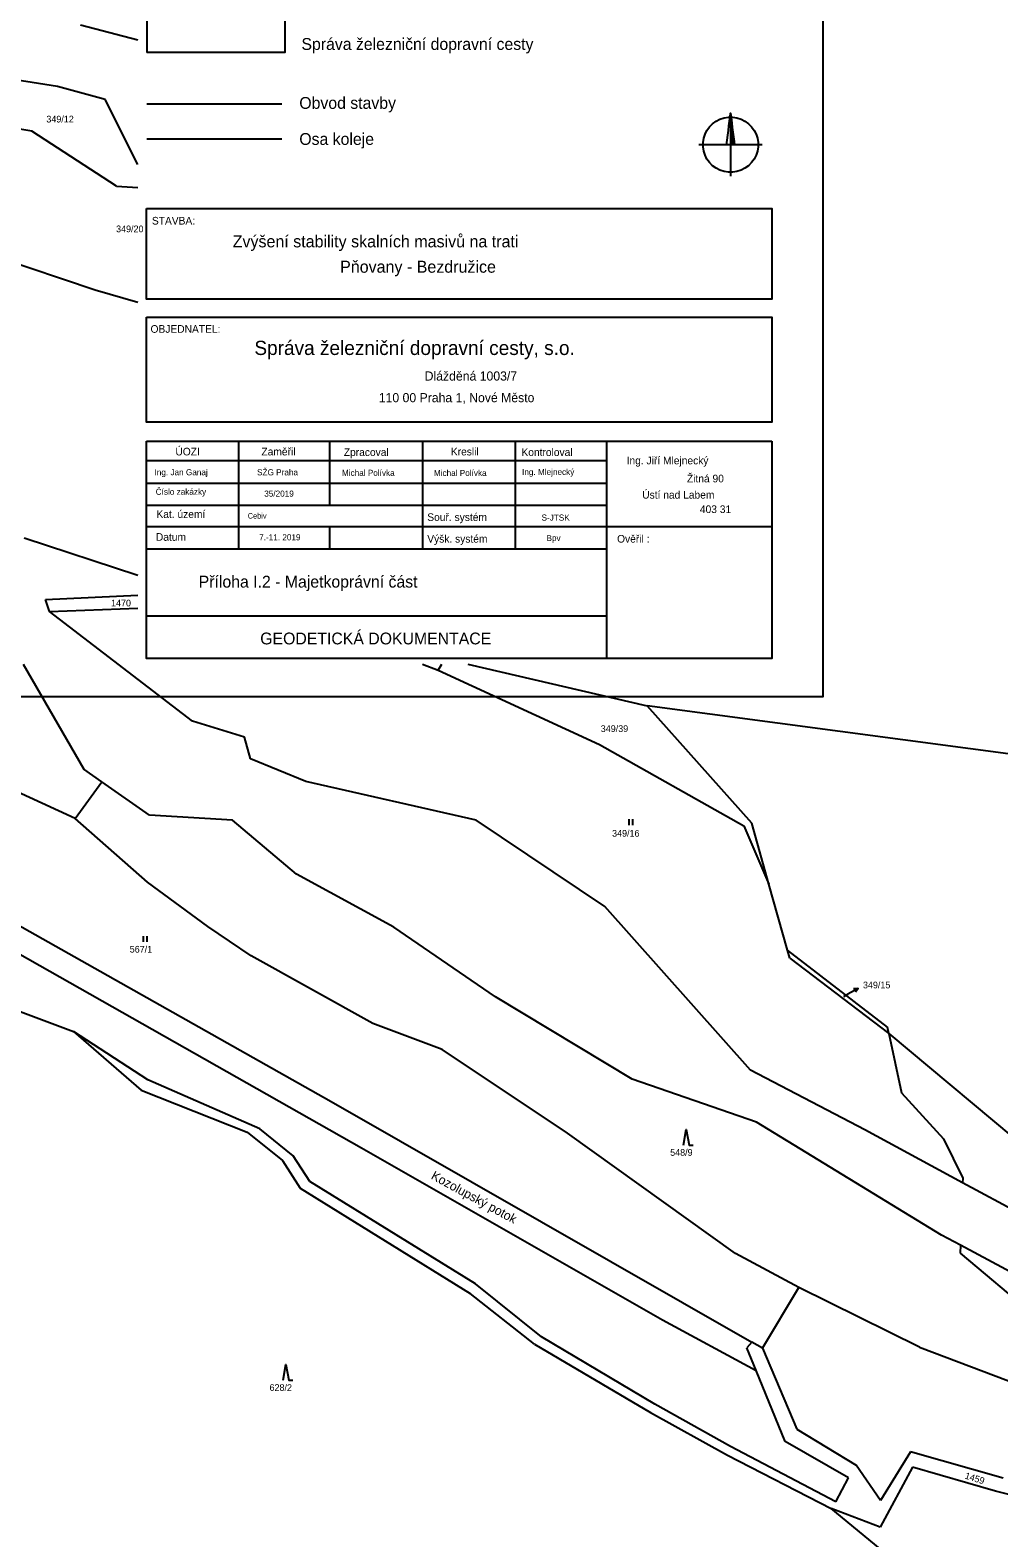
# Model space of a CAD drawing. Extents: x -852001 to -842497, y -1063614 to -1052182.
# Drawn here: x -848517.5 to -848271.7, y -1057263.9 to -1056881.4 of the extents above; entities that cross this region are included whole.
import ezdxf

# ---------------------------------------------------------------- set-up
doc = ezdxf.new("R2010")
doc.units = 0
for name, color, linetype in [('Default', 7, 'Continuous'), ('KN_HRANICE', 7, 'Continuous'), ('KN_KULTURY', 7, 'Continuous'), ('KN_PARCELY', 7, 'Continuous'), ('LEGENDA', 7, 'Continuous'), ('tabulka', 7, 'Continuous')]:
    doc.layers.add(name, color=color, linetype=linetype)

# ---------------------------------------------------------------- blocks, each defined once
blk = doc.blocks.new('306')
at = {"layer": 'Default'}
for p, q in [((-0.5, 1.5), (-0.5, 0)), ((0.5, 0), (0.5, 1.5))]:
    blk.add_line(p, q, dxfattribs=at)
blk = doc.blocks.new('308')
at = {"layer": 'Default'}
blk.add_lwpolyline([(-0.75, 0), (0, 4), (0.75, 0), (1.75, 0)], dxfattribs=at)
blk = doc.blocks.new('10292')
at = {"layer": 'Default'}
blk.add_line((0, 3), (0, 0), dxfattribs=at)
blk.add_lwpolyline([(-0.5, 2), (0, 3), (0.5, 2)], dxfattribs=at)
blk = doc.blocks.new('SEVER')
at = {"layer": 'Default'}
for points in [[(-10, 0), (-8.5, 12), (-7, 24), (-5.5, 36), (-4, 48), (-2.5, 60), (-1, 72), (0, 80), (1.5, 68), (3, 56), (4.5, 44), (6, 32), (7.5, 20), (9, 8), (10, 0), (9.2, 0.8), (9.2, 5.6), (8.4, 12), (8.4, 0.8), (7.6, 0.8), (7.6, 13.5), (7.6, 18.4), (6.8, 24.8), (6.8, 12.1), (6.8, 0.8), (6, 0.8), (6, 13.5), (6, 26.2), (6, 31.2), (5.2, 36.8), (5.2, 24.1), (5.2, 11.4), (5.2, 0.8), (4.4, 0.8), (4.4, 13.5), (4.4, 26.2), (4.4, 38.9), (4.4, 43.2), (3.6, 50.4), (3.6, 37.7), (3.6, 25), (3.6, 12.3), (3.6, 0.8), (2.8, 0.8), (2.8, 13.5), (2.8, 26.2), (2.8, 38.9), (2.8, 51.6), (2.8, 56), (2, 63.2), (2, 50.5), (2, 37.8), (2, 25.1), (2, 12.4), (2, 0.8), (1.2, 0.8), (1.2, 13.5), (1.2, 26.2), (1.2, 38.9), (1.2, 51.6), (1.2, 64.3), (1.2, 69.6), (0.4, 76), (0.4, 63.3), (0.4, 50.6), (0.4, 37.9), (0.4, 25.2), (0.4, 12.5), (0.4, 0.8)], [(0, 80), (0, 67.3), (0, 54.6), (0, 41.9), (0, 29.2), (0, 16.5), (0, 3.8), (0, -8.9), (0, -21.6), (0, -34.3), (0, -47), (0, -59.7), (0, -72.4), (0, -80)], [(5.5, 69.8), (16.3, 68.1), (26.7, 64.7), (36.5, 59.7), (45.4, 53.2), (53.2, 45.4), (59.7, 36.5), (64.7, 26.7), (68.1, 16.3), (69.8, 5.5), (69.8, -5.5), (68.1, -16.3), (64.7, -26.7), (59.7, -36.5), (53.2, -45.4), (45.4, -53.2), (36.5, -59.7), (26.7, -64.7), (16.3, -68.1), (5.5, -69.8), (-5.5, -69.8), (-16.3, -68.1), (-26.7, -64.7), (-36.5, -59.7), (-45.4, -53.2), (-53.2, -45.4), (-59.7, -36.5), (-64.7, -26.7), (-68.1, -16.3), (-69.8, -5.5), (-69.8, 5.5), (-68.1, 16.3), (-64.7, 26.7), (-59.7, 36.5), (-53.2, 45.4), (-45.4, 53.2), (-36.5, 59.7), (-26.7, 64.7), (-16.3, 68.1), (-5.5, 69.8), (5.5, 69.8)], [(80, 0), (67.3, 0), (54.6, 0), (41.9, 0), (29.2, 0), (16.5, 0), (3.8, 0), (-8.9, 0), (-21.6, 0), (-34.3, 0), (-47, 0), (-59.7, 0), (-72.4, 0), (-80, 0)]]:
    blk.add_lwpolyline(points, dxfattribs=at)

msp = doc.modelspace()

# ---------------------------------------------------------------- linework, layer by layer
at = {"layer": 'KN_HRANICE'}
for p, q in [((-848504.72, -1056880.07), (-848490.15, -1056883.83)), ((-848510.51, -1056895.7), (-848533.12, -1056892.09)), ((-848498.47, -1056899.01), (-848510.51, -1056895.7)), ((-848490.15, -1056915.49), (-848498.47, -1056899.01)), ((-848517.02, -1056907.05), (-848536, -1056903.82)), ((-848495.58, -1056920.99), (-848517.02, -1056907.05)), ((-848495.58, -1056920.99), (-848490.15, -1056921.28)), ((-848537.27, -1056935.01), (-848500.98, -1056947.31)), ((-848500.98, -1056947.31), (-848490.15, -1056950.37)), ((-848518.98, -1057010.18), (-848490.15, -1057019.65)), ((-848513.63, -1057025.87), (-848490.15, -1057024.73)), ((-848512.6, -1057028.9), (-848513.63, -1057025.87)), ((-848512.6, -1057028.9), (-848490.15, -1057028.02)), ((-848476.32, -1057056.74), (-848512.6, -1057028.9)), ((-848417.96, -1057042.22), (-848414, -1057043.75)), ((-848414, -1057043.75), (-848413.02, -1057042.22)), ((-848406.4, -1057042.22), (-848360.93, -1057052.81)), ((-848519.3, -1057042.27), (-848503.9, -1057068.91)), ((-848414, -1057043.75), (-848373.02, -1057062.67)), ((-848215.69, -1057072.14), (-848360.93, -1057052.81)), ((-848334.41, -1057082.61), (-848360.93, -1057052.81)), ((-848463.07, -1057060.76), (-848476.32, -1057056.74)), ((-848461.56, -1057066.3), (-848463.07, -1057060.76)), ((-848506.04, -1057081.45), (-848549.47, -1057061.41)), ((-848373.02, -1057062.67), (-848336.42, -1057083.27)), ((-848499.28, -1057072.14), (-848503.9, -1057068.91)), ((-848447.56, -1057072), (-848461.56, -1057066.3)), ((-848506.04, -1057081.45), (-848499.28, -1057072.14)), ((-848487.18, -1057080.6), (-848499.28, -1057072.14)), ((-848404.36, -1057081.83), (-848447.56, -1057072)), ((-848487.71, -1057097.61), (-848506.04, -1057081.45)), ((-848466.12, -1057081.86), (-848487.18, -1057080.6)), ((-848449.89, -1057095.52), (-848466.12, -1057081.86)), ((-848371.65, -1057103.72), (-848404.36, -1057081.83)), ((-848336.42, -1057083.27), (-848330.02, -1057098.12)), ((-848330.02, -1057098.12), (-848334.41, -1057082.61)), ((-848425.24, -1057108.98), (-848449.89, -1057095.52)), ((-848472.4, -1057108.82), (-848487.71, -1057097.61)), ((-848325.31, -1057114.79), (-848330.02, -1057098.12)), ((-848530.27, -1057102.96), (-848441.09, -1057153.24)), ((-848334.72, -1057145.28), (-848371.65, -1057103.72)), ((-848461.38, -1057116.29), (-848472.4, -1057108.82)), ((-848399.37, -1057126.68), (-848425.24, -1057108.98)), ((-848523.24, -1057114.03), (-848433.37, -1057164.99)), ((-848324.73, -1057116.84), (-848325.31, -1057114.79)), ((-848299.92, -1057134.4), (-848325.31, -1057114.79)), ((-848553.53, -1057117.8), (-848506.45, -1057135.5)), ((-848430.53, -1057133.44), (-848461.38, -1057116.29)), ((-848324.73, -1057116.84), (-848299.58, -1057135.99)), ((-848364.72, -1057147.55), (-848399.37, -1057126.68)), ((-848412.95, -1057140.06), (-848430.53, -1057133.44)), ((-848487.59, -1057147.75), (-848506.45, -1057135.5)), ((-848506.45, -1057135.5), (-848489.36, -1057150.38)), ((-848299.58, -1057135.99), (-848299.92, -1057134.4)), ((-848299.58, -1057135.99), (-848233.15, -1057191.58)), ((-848299.58, -1057135.99), (-848296.41, -1057151.03)), ((-848381.12, -1057161.25), (-848412.95, -1057140.06)), ((-848305.73, -1057160.43), (-848334.72, -1057145.28)), ((-848459.18, -1057160.12), (-848487.59, -1057147.75)), ((-848333.2, -1057158.46), (-848364.72, -1057147.55)), ((-848489.36, -1057150.38), (-848462.42, -1057161.04)), ((-848296.41, -1057151.03), (-848285.71, -1057162.73)), ((-848441.09, -1057153.24), (-848334.38, -1057214.31)), ((-848450.79, -1057166.98), (-848459.18, -1057160.12)), ((-848286.21, -1057187.14), (-848333.2, -1057158.46)), ((-848280.88, -1057173.84), (-848305.73, -1057160.43)), ((-848462.42, -1057161.04), (-848453.48, -1057168.21)), ((-848338.5, -1057191.75), (-848381.12, -1057161.25)), ((-848285.71, -1057162.73), (-848280.84, -1057172.68)), ((-848453.48, -1057168.21), (-848449.01, -1057175.25)), ((-848446.5, -1057173.48), (-848450.79, -1057166.98)), ((-848433.37, -1057164.99), (-848357, -1057208.66)), ((-848449.01, -1057175.25), (-848405.84, -1057201.9)), ((-848404.5, -1057199.51), (-848446.5, -1057173.48)), ((-848280.84, -1057172.68), (-848280.88, -1057173.84)), ((-848266.13, -1057181.8), (-848280.88, -1057173.84)), ((-848281.42, -1057189.71), (-848286.21, -1057187.14)), ((-848281.42, -1057189.71), (-848281.49, -1057191.69)), ((-848262.98, -1057199.6), (-848281.42, -1057189.71)), ((-848322.41, -1057200.38), (-848338.5, -1057191.75)), ((-848281.49, -1057191.69), (-848258.56, -1057211.07)), ((-848389.49, -1057214.83), (-848405.84, -1057201.9)), ((-848387.72, -1057212.93), (-848404.5, -1057199.51)), ((-848331.65, -1057215.79), (-848322.41, -1057200.38)), ((-848291.86, -1057215.56), (-848322.41, -1057200.38)), ((-848357, -1057208.66), (-848333.29, -1057221.51)), ((-848359, -1057230.02), (-848387.72, -1057212.93)), ((-848334.38, -1057214.31), (-848335.67, -1057215.72)), ((-848331.65, -1057215.79), (-848334.38, -1057214.31)), ((-848389.49, -1057214.83), (-848360.1, -1057232.1)), ((-848333.29, -1057221.51), (-848335.67, -1057215.72)), ((-848331.65, -1057215.79), (-848322.99, -1057236.35)), ((-848291.86, -1057215.56), (-848236.63, -1057236.51)), ((-848325.9, -1057239.53), (-848333.29, -1057221.51)), ((-848360.1, -1057232.1), (-848340.57, -1057242.94)), ((-848339.78, -1057240.74), (-848359, -1057230.02)), ((-848322.99, -1057236.35), (-848307.86, -1057245.53)), ((-848313.04, -1057254.78), (-848339.78, -1057240.74)), ((-848309.85, -1057248.75), (-848325.9, -1057239.53)), ((-848340.57, -1057242.94), (-848314.23, -1057256.53)), ((-848294.1, -1057242.15), (-848301.7, -1057254.43)), ((-848270.59, -1057248.8), (-848294.1, -1057242.15)), ((-848313.04, -1057254.78), (-848309.85, -1057248.75)), ((-848301.7, -1057254.43), (-848307.86, -1057245.53)), ((-848293.61, -1057246), (-848301.77, -1057261.22)), ((-848272.56, -1057252.1), (-848293.61, -1057246)), ((-848254.71, -1057256.58), (-848272.56, -1057252.1)), ((-848301.77, -1057261.22), (-848314.23, -1057256.53)), ((-848263.91, -1057297.71), (-848314.23, -1057256.53))]:
    msp.add_line(p, q, dxfattribs=at)
at = {"layer": 'KN_PARCELY'}
msp.add_line((-848311.02, -1057126.58), (-848310.02, -1057126.01), dxfattribs=at)
at = {"layer": 'LEGENDA'}
for p, q in [((-848487.86, -1056877.05), (-848487.86, -1056887.05)), ((-848487.84, -1056900.09), (-848453.65, -1056900.09)), ((-848487.84, -1056908.92), (-848453.65, -1056908.92))]:
    msp.add_line(p, q, dxfattribs=at)
msp.add_lwpolyline([(-848910.31, -1057050.45), (-848316.31, -1057050.45), (-848316.31, -1056630.45), (-848910.31, -1056630.45)], close=True, dxfattribs=at)
msp.add_lwpolyline([(-848452.86, -1056877.05), (-848452.86, -1056887.05), (-848487.86, -1056887.05)], dxfattribs=at)
at = {"layer": 'tabulka'}
for p, q in [((-848487.93, -1056985.69), (-848329.28, -1056985.69)), ((-848464.65, -1056985.69), (-848464.65, -1057013.01)), ((-848441.5, -1056985.69), (-848441.5, -1057001.89)), ((-848417.9, -1056985.69), (-848417.9, -1057013.01)), ((-848394.45, -1056985.69), (-848394.45, -1057013.01)), ((-848371.15, -1057040.83), (-848371.15, -1056985.69)), ((-848487.93, -1056990.6), (-848371.15, -1056990.6)), ((-848487.93, -1056996.32), (-848371.15, -1056996.32)), ((-848487.93, -1057001.89), (-848371.15, -1057001.89)), ((-848487.93, -1057007.31), (-848329.28, -1057007.31)), ((-848441.5, -1057007.31), (-848441.5, -1057013.01)), ((-848487.93, -1057013.01), (-848371.15, -1057013.01)), ((-848487.93, -1057030.01), (-848371.15, -1057030.01))]:
    msp.add_line(p, q, dxfattribs=at)
for points in [[(-848487.93, -1056926.61), (-848329.28, -1056926.61), (-848329.28, -1056949.67), (-848487.93, -1056949.67)], [(-848487.93, -1056954.19), (-848329.28, -1056954.19), (-848329.28, -1056980.88), (-848487.93, -1056980.88)]]:
    msp.add_lwpolyline(points, close=True, dxfattribs=at)
msp.add_lwpolyline([(-848329.28, -1056985.69), (-848329.28, -1057040.83), (-848487.93, -1057040.83), (-848487.93, -1056985.69)], dxfattribs=at)

# ---------------------------------------------------------------- block references
at = {"layer": 'KN_KULTURY'}
for name, p in [('306', (-848365.04, -1057083.1)), ('306', (-848488.33, -1057112.74)), ('308', (-848351, -1057164.3)), ('308', (-848452.58, -1057223.96))]:
    msp.add_blockref(name, p, dxfattribs=at)
at = {"layer": 'KN_PARCELY', "rotation": -60.11389}
msp.add_blockref('10292', (-848310.02, -1057126.01), dxfattribs=at)
at = {"layer": 'LEGENDA', "xscale": 0.1, "yscale": 0.10000000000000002}
msp.add_blockref('SEVER', (-848339.78, -1056910.46), dxfattribs=at)

# ---------------------------------------------------------------- texts
at = {"layer": 'KN_PARCELY'}
for s, height, p in [('349/12', 1.7, (-848513.37, -1056904.81)), ('349/20', 1.7, (-848495.68, -1056932.66)), ('1470', 1.7, (-848496.96, -1057027.6)), ('349/39', 1.7, (-848372.7, -1057059.46)), ('349/16', 1.7, (-848369.83, -1057086.03)), ('567/1', 1.7, (-848492.22, -1057115.44)), ('349/15', 1.7, (-848306.18, -1057124.51)), ('349/15', 0.1, (-848311.31, -1057126.58)), ('548/9', 1.7, (-848355.09, -1057167)), ('628/2', 1.7, (-848456.75, -1057226.66))]:
    msp.add_text(s, height=height, dxfattribs=at).set_placement(p)
for s, height, rotation, p in [('Kozolupský potok', 2.3, 331.399, (-848415.96, -1057172.75)), ('1459', 1.7, 342.514, (-848280.47, -1057248.87))]:
    msp.add_text(s, height=height, rotation=rotation, dxfattribs=at).set_placement(p)
at = {"layer": 'LEGENDA'}
for s, height, p in [('Správa železniční dopravní cesty', 3, (-848448.65, -1056886.4)), ('Obvod stavby', 3, (-848449.19, -1056901.35)), ('Osa koleje', 3, (-848449.19, -1056910.5)), ('Zvýšení stability skalních masivů na trati', 3.04, (-848466.1, -1056936.5)), ('Pňovany - Bezdružice', 3.04, (-848438.84, -1056942.93))]:
    msp.add_text(s, height=height, dxfattribs=at).set_placement(p)
at = {"layer": 'tabulka'}
for s, height, p in [('STAVBA:', 1.94, (-848486.59, -1056930.71)), ('OBJEDNATEL:', 1.94, (-848486.94, -1056958.17)), ('Správa železniční dopravní cesty, s.o.', 3.61, (-848460.59, -1056963.81)), ('Dlážděná 1003/7', 2.32, (-848417.39, -1056970.3)), ('110 00 Praha 1, Nové Město', 2.32, (-848429.03, -1056975.79)), ('ÚOZI', 1.94, (-848480.63, -1056989.29)), ('Zaměřil', 1.94, (-848458.8, -1056989.29)), ('Zpracoval', 1.94, (-848437.9, -1056989.44)), ('Kreslil', 1.94, (-848410.74, -1056989.29)), ('Kontroloval', 1.94, (-848392.83, -1056989.44)), ('SŽG Praha', 1.552, (-848459.91, -1056994.35)), ('Ing. Jiří Mlejnecký', 1.94, (-848366.14, -1056991.55)), ('Ing. Jan Ganaj', 1.552, (-848485.92, -1056994.33)), ('Michal Polívka', 1.552, (-848438.38, -1056994.48)), ('Michal Polívka', 1.552, (-848415.05, -1056994.51)), ('Ing. Mlejnecký', 1.552, (-848392.68, -1056994.25)), ('Žitná 90', 1.94, (-848350.84, -1056996.13)), ('Číslo zakázky', 1.552, (-848485.63, -1056999.28)), ('35/2019', 1.552, (-848458.09, -1056999.76)), ('Ústí nad Labem', 1.94, (-848362.18, -1057000.25)), ('Kat. území', 1.94, (-848485.44, -1057005.16)), ('Cebiv', 1.397, (-848462.27, -1057005.32)), ('Souř. systém', 1.94, (-848416.72, -1057005.92)), ('403 31', 1.94, (-848347.55, -1057003.91)), ('S-JTSK', 1.552, (-848387.73, -1057005.84)), ('Datum', 1.94, (-848485.58, -1057010.95)), ('7.-11. 2019', 1.552, (-848459.38, -1057010.84)), ('Výšk. systém', 1.94, (-848416.73, -1057011.41)), ('Bpv', 1.552, (-848386.46, -1057011.02)), ('Ověřil :', 1.94, (-848368.56, -1057011.41)), ('Příloha I.2 - Majetkoprávní část', 3, (-848474.72, -1057022.82)), ('GEODETICKÁ DOKUMENTACE ', 3, (-848459.11, -1057037.24))]:
    msp.add_text(s, height=height, dxfattribs=at).set_placement(p)

doc.saveas('drawing.dxf')
